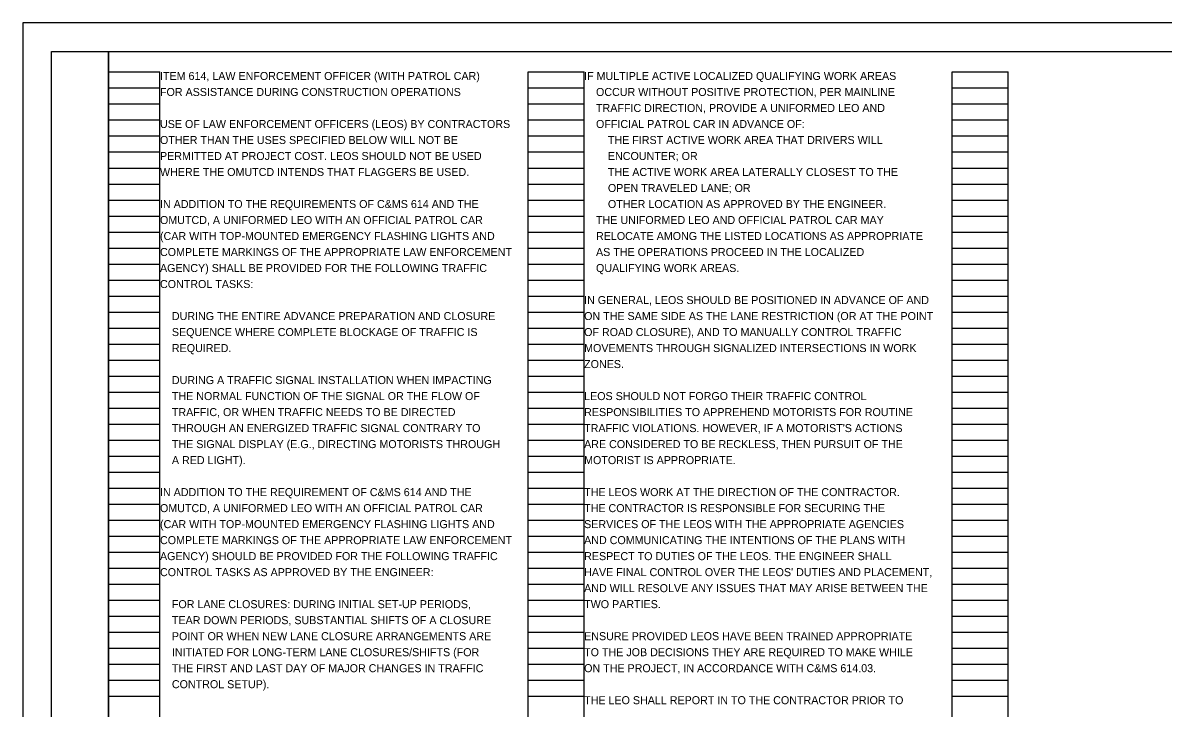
# Model space of a CAD drawing. Extents: x 0 to 34, y -2.1 to 22.
# Drawn here: x 0 to 19.95, y 10.01 to 22 of the extents above; entities that cross this region are included whole.
import ezdxf

# ---------------------------------------------------------------- set-up
doc = ezdxf.new("R2010")
doc.units = 0
for name, color, linetype in [('SH_Border', 7, 'Continuous'), ('SH_Cut_Line', 7, 'Continuous'), ('SH_Data', 7, 'Continuous'), ('SH_Text', 7, 'Continuous')]:
    doc.layers.add(name, color=color, linetype=linetype)

msp = doc.modelspace()

# ---------------------------------------------------------------- linework, layer by layer
at = {"layer": 'SH_Border'}
for points in [[(0.5, 21.5), (1.5, 21.5), (1.5, 0.5), (0.5, 0.5)], [(1.5, 21.5), (33.5, 21.5), (33.5, 0.5), (1.5, 0.5)]]:
    msp.add_lwpolyline(points, close=True, dxfattribs=at)
at = {"layer": 'SH_Cut_Line'}
msp.add_lwpolyline([(0, 0), (34, 0), (34, 22), (0, 22)], close=True, dxfattribs=at)
at = {"layer": 'SH_Data'}
for p, q in [((1.5, 0.98), (1.5, 21.14)), ((1.5, 21.14), (2.4, 21.14)), ((2.4, 0.98), (2.4, 21.14)), ((8.84, 0.98), (8.84, 21.14)), ((8.84, 21.14), (9.82, 21.14)), ((9.82, 0.98), (9.82, 21.14)), ((16.26, 0.98), (16.26, 21.14)), ((16.26, 21.14), (17.24, 21.14)), ((17.24, 0.98), (17.24, 21.14)), ((1.5, 20.86), (2.4, 20.86)), ((8.84, 20.86), (9.82, 20.86)), ((16.26, 20.86), (17.24, 20.86)), ((1.5, 20.58), (2.4, 20.58)), ((8.84, 20.58), (9.82, 20.58)), ((16.26, 20.58), (17.24, 20.58)), ((1.5, 20.3), (2.4, 20.3)), ((8.84, 20.3), (9.82, 20.3)), ((16.26, 20.3), (17.24, 20.3)), ((1.5, 20.02), (2.4, 20.02)), ((8.84, 20.02), (9.82, 20.02)), ((16.26, 20.02), (17.24, 20.02)), ((1.5, 19.74), (2.4, 19.74)), ((8.84, 19.74), (9.82, 19.74)), ((16.26, 19.74), (17.24, 19.74)), ((1.5, 19.46), (2.4, 19.46)), ((8.84, 19.46), (9.82, 19.46)), ((16.26, 19.46), (17.24, 19.46)), ((1.5, 19.18), (2.4, 19.18)), ((8.84, 19.18), (9.82, 19.18)), ((16.26, 19.18), (17.24, 19.18)), ((1.5, 18.9), (2.4, 18.9)), ((8.84, 18.9), (9.82, 18.9)), ((16.26, 18.9), (17.24, 18.9)), ((1.5, 18.62), (2.4, 18.62)), ((8.84, 18.62), (9.82, 18.62)), ((16.26, 18.62), (17.24, 18.62)), ((1.5, 18.34), (2.4, 18.34)), ((8.84, 18.34), (9.82, 18.34)), ((16.26, 18.34), (17.24, 18.34)), ((1.5, 18.06), (2.4, 18.06)), ((8.84, 18.06), (9.82, 18.06)), ((16.26, 18.06), (17.24, 18.06)), ((1.5, 17.78), (2.4, 17.78)), ((8.84, 17.78), (9.82, 17.78)), ((16.26, 17.78), (17.24, 17.78)), ((1.5, 17.5), (2.4, 17.5)), ((8.84, 17.5), (9.82, 17.5)), ((16.26, 17.5), (17.24, 17.5)), ((1.5, 17.22), (2.4, 17.22)), ((8.84, 17.22), (9.82, 17.22)), ((16.26, 17.22), (17.24, 17.22)), ((1.5, 16.94), (2.4, 16.94)), ((8.84, 16.94), (9.82, 16.94)), ((16.26, 16.94), (17.24, 16.94)), ((1.5, 16.66), (2.4, 16.66)), ((8.84, 16.66), (9.82, 16.66)), ((16.26, 16.66), (17.24, 16.66)), ((1.5, 16.38), (2.4, 16.38)), ((8.84, 16.38), (9.82, 16.38)), ((16.26, 16.38), (17.24, 16.38)), ((1.5, 16.1), (2.4, 16.1)), ((8.84, 16.1), (9.82, 16.1)), ((16.26, 16.1), (17.24, 16.1)), ((1.5, 15.82), (2.4, 15.82)), ((8.84, 15.82), (9.82, 15.82)), ((16.26, 15.82), (17.24, 15.82)), ((1.5, 15.54), (2.4, 15.54)), ((8.84, 15.54), (9.82, 15.54)), ((16.26, 15.54), (17.24, 15.54)), ((1.5, 15.26), (2.4, 15.26)), ((8.84, 15.26), (9.82, 15.26)), ((16.26, 15.26), (17.24, 15.26)), ((1.5, 14.98), (2.4, 14.98)), ((8.84, 14.98), (9.82, 14.98)), ((16.26, 14.98), (17.24, 14.98)), ((1.5, 14.7), (2.4, 14.7)), ((8.84, 14.7), (9.82, 14.7)), ((16.26, 14.7), (17.24, 14.7)), ((1.5, 14.42), (2.4, 14.42)), ((8.84, 14.42), (9.82, 14.42)), ((16.26, 14.42), (17.24, 14.42)), ((1.5, 14.14), (2.4, 14.14)), ((8.84, 14.14), (9.82, 14.14)), ((16.26, 14.14), (17.24, 14.14)), ((1.5, 13.86), (2.4, 13.86)), ((8.84, 13.86), (9.82, 13.86)), ((16.26, 13.86), (17.24, 13.86)), ((1.5, 13.58), (2.4, 13.58)), ((8.84, 13.58), (9.82, 13.58)), ((16.26, 13.58), (17.24, 13.58)), ((1.5, 13.3), (2.4, 13.3)), ((8.84, 13.3), (9.82, 13.3)), ((16.26, 13.3), (17.24, 13.3)), ((1.5, 13.02), (2.4, 13.02)), ((8.84, 13.02), (9.82, 13.02)), ((16.26, 13.02), (17.24, 13.02)), ((1.5, 12.74), (2.4, 12.74)), ((8.84, 12.74), (9.82, 12.74)), ((16.26, 12.74), (17.24, 12.74)), ((1.5, 12.46), (2.4, 12.46)), ((8.84, 12.46), (9.82, 12.46)), ((16.26, 12.46), (17.24, 12.46)), ((1.5, 12.18), (2.4, 12.18)), ((8.84, 12.18), (9.82, 12.18)), ((16.26, 12.18), (17.24, 12.18)), ((1.5, 11.9), (2.4, 11.9)), ((8.84, 11.9), (9.82, 11.9)), ((16.26, 11.9), (17.24, 11.9)), ((1.5, 11.62), (2.4, 11.62)), ((8.84, 11.62), (9.82, 11.62)), ((16.26, 11.62), (17.24, 11.62)), ((1.5, 11.34), (2.4, 11.34)), ((8.84, 11.34), (9.82, 11.34)), ((16.26, 11.34), (17.24, 11.34)), ((1.5, 11.06), (2.4, 11.06)), ((8.84, 11.06), (9.82, 11.06)), ((16.26, 11.06), (17.24, 11.06)), ((1.5, 10.78), (2.4, 10.78)), ((8.84, 10.78), (9.82, 10.78)), ((16.26, 10.78), (17.24, 10.78)), ((1.5, 10.5), (2.4, 10.5)), ((8.84, 10.5), (9.82, 10.5)), ((16.26, 10.5), (17.24, 10.5)), ((1.5, 10.22), (2.4, 10.22)), ((8.84, 10.22), (9.82, 10.22)), ((16.26, 10.22), (17.24, 10.22))]:
    msp.add_line(p, q, dxfattribs=at)

# ---------------------------------------------------------------- texts
at = {"layer": 'SH_Text'}
for s, p in [('ITEM 614, LAW ENFORCEMENT OFFICER (WITH PATROL CAR)', (2.4, 21)), ('IF MULTIPLE ACTIVE LOCALIZED QUALIFYING WORK AREAS', (9.82, 21)), ('FOR ASSISTANCE DURING CONSTRUCTION OPERATIONS', (2.4, 20.72)), ('    OCCUR WITHOUT POSITIVE PROTECTION, PER MAINLINE', (9.82, 20.72)), ('    TRAFFIC DIRECTION, PROVIDE A UNIFORMED LEO AND', (9.82, 20.44)), ('USE OF LAW ENFORCEMENT OFFICERS (LEOS) BY CONTRACTORS', (2.4, 20.16)), ('    OFFICIAL PATROL CAR IN ADVANCE OF:', (9.82, 20.16)), ('OTHER THAN THE USES SPECIFIED BELOW WILL NOT BE', (2.4, 19.88)), ('        THE FIRST ACTIVE WORK AREA THAT DRIVERS WILL', (9.82, 19.88)), ('PERMITTED AT PROJECT COST. LEOS SHOULD NOT BE USED', (2.4, 19.6)), ('        ENCOUNTER; OR', (9.82, 19.6)), ('WHERE THE OMUTCD INTENDS THAT FLAGGERS BE USED.', (2.4, 19.32)), ('        THE ACTIVE WORK AREA LATERALLY CLOSEST TO THE', (9.82, 19.32)), ('        OPEN TRAVELED LANE; OR', (9.82, 19.04)), ('IN ADDITION TO THE REQUIREMENTS OF C&MS 614 AND THE', (2.4, 18.76)), ('        OTHER LOCATION AS APPROVED BY THE ENGINEER.', (9.82, 18.76)), ('OMUTCD, A UNIFORMED LEO WITH AN OFFICIAL PATROL CAR', (2.4, 18.48)), ('    THE UNIFORMED LEO AND OFFICIAL PATROL CAR MAY', (9.82, 18.48)), ('(CAR WITH TOP-MOUNTED EMERGENCY FLASHING LIGHTS AND', (2.4, 18.2)), ('    RELOCATE AMONG THE LISTED LOCATIONS AS APPROPRIATE', (9.82, 18.2)), ('COMPLETE MARKINGS OF THE APPROPRIATE LAW ENFORCEMENT', (2.4, 17.92)), ('    AS THE OPERATIONS PROCEED IN THE LOCALIZED', (9.82, 17.92)), ('AGENCY) SHALL BE PROVIDED FOR THE FOLLOWING TRAFFIC', (2.4, 17.64)), ('    QUALIFYING WORK AREAS.', (9.82, 17.64)), ('CONTROL TASKS:', (2.4, 17.36)), ('IN GENERAL, LEOS SHOULD BE POSITIONED IN ADVANCE OF AND', (9.82, 17.08)), ('    DURING THE ENTIRE ADVANCE PREPARATION AND CLOSURE', (2.4, 16.8)), ('ON THE SAME SIDE AS THE LANE RESTRICTION (OR AT THE POINT', (9.82, 16.8)), ('    SEQUENCE WHERE COMPLETE BLOCKAGE OF TRAFFIC IS', (2.4, 16.52)), ('OF ROAD CLOSURE), AND TO MANUALLY CONTROL TRAFFIC', (9.82, 16.52)), ('    REQUIRED.', (2.4, 16.24)), ('MOVEMENTS THROUGH SIGNALIZED INTERSECTIONS IN WORK', (9.82, 16.24)), ('ZONES.', (9.82, 15.96)), ('    DURING A TRAFFIC SIGNAL INSTALLATION WHEN IMPACTING', (2.4, 15.68)), ('    THE NORMAL FUNCTION OF THE SIGNAL OR THE FLOW OF', (2.4, 15.4)), ('LEOS SHOULD NOT FORGO THEIR TRAFFIC CONTROL', (9.82, 15.4)), ('    TRAFFIC, OR WHEN TRAFFIC NEEDS TO BE DIRECTED', (2.4, 15.12)), ('RESPONSIBILITIES TO APPREHEND MOTORISTS FOR ROUTINE', (9.82, 15.12)), ('    THROUGH AN ENERGIZED TRAFFIC SIGNAL CONTRARY TO', (2.4, 14.84)), ("TRAFFIC VIOLATIONS. HOWEVER, IF A MOTORIST'S ACTIONS", (9.82, 14.84)), ('    THE SIGNAL DISPLAY (E.G., DIRECTING MOTORISTS THROUGH', (2.4, 14.56)), ('ARE CONSIDERED TO BE RECKLESS, THEN PURSUIT OF THE', (9.82, 14.56)), ('    A RED LIGHT).', (2.4, 14.28)), ('MOTORIST IS APPROPRIATE.', (9.82, 14.28)), ('IN ADDITION TO THE REQUIREMENT OF C&MS 614 AND THE', (2.4, 13.72)), ('THE LEOS WORK AT THE DIRECTION OF THE CONTRACTOR.', (9.82, 13.72)), ('OMUTCD, A UNIFORMED LEO WITH AN OFFICIAL PATROL CAR', (2.4, 13.44)), ('THE CONTRACTOR IS RESPONSIBLE FOR SECURING THE', (9.82, 13.44)), ('(CAR WITH TOP-MOUNTED EMERGENCY FLASHING LIGHTS AND', (2.4, 13.16)), ('SERVICES OF THE LEOS WITH THE APPROPRIATE AGENCIES', (9.82, 13.16)), ('COMPLETE MARKINGS OF THE APPROPRIATE LAW ENFORCEMENT', (2.4, 12.88)), ('AND COMMUNICATING THE INTENTIONS OF THE PLANS WITH', (9.82, 12.88)), ('AGENCY) SHOULD BE PROVIDED FOR THE FOLLOWING TRAFFIC', (2.4, 12.6)), ('RESPECT TO DUTIES OF THE LEOS. THE ENGINEER SHALL', (9.82, 12.6)), ('CONTROL TASKS AS APPROVED BY THE ENGINEER:', (2.4, 12.32)), ("HAVE FINAL CONTROL OVER THE LEOS' DUTIES AND PLACEMENT,", (9.82, 12.32)), ('AND WILL RESOLVE ANY ISSUES THAT MAY ARISE BETWEEN THE', (9.82, 12.04)), ('    FOR LANE CLOSURES: DURING INITIAL SET-UP PERIODS,', (2.4, 11.76)), ('TWO PARTIES.', (9.82, 11.76)), ('    TEAR DOWN PERIODS, SUBSTANTIAL SHIFTS OF A CLOSURE', (2.4, 11.48)), ('    POINT OR WHEN NEW LANE CLOSURE ARRANGEMENTS ARE', (2.4, 11.2)), ('ENSURE PROVIDED LEOS HAVE BEEN TRAINED APPROPRIATE', (9.82, 11.2)), ('    INITIATED FOR LONG-TERM LANE CLOSURES/SHIFTS (FOR', (2.4, 10.92)), ('TO THE JOB DECISIONS THEY ARE REQUIRED TO MAKE WHILE', (9.82, 10.92)), ('    THE FIRST AND LAST DAY OF MAJOR CHANGES IN TRAFFIC', (2.4, 10.64)), ('ON THE PROJECT, IN ACCORDANCE WITH C&MS 614.03.', (9.82, 10.64)), ('    CONTROL SETUP).', (2.4, 10.36)), ('THE LEO SHALL REPORT IN TO THE CONTRACTOR PRIOR TO', (9.82, 10.08))]:
    msp.add_text(s, height=0.14, dxfattribs=at).set_placement(p)

doc.saveas('drawing.dxf')
